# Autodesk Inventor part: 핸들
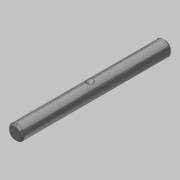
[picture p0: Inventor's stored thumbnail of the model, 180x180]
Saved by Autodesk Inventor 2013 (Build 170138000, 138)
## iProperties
Created: 2019-04
Part Number: 핸들
Material: 스테인리스강
Document SubType Name: Modeling
Designer: mduedu
Density: 1 g/cm^3
Author: mduedu
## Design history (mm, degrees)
sketch "스케치1"
  geometry: C1 r 4 at (0, 0); 1 further point
  constraints: 1 centre point, 1 coincident
  dimensions: "d0" = 8 diameter of C1
extrude "돌출1" new body sketch "스케치1" stored distance "d1" = 80; taper "d2" = 0 deg
chamfer "모따기1" distance "d3" = 1; stored, may be unused: second distance "d4" = 2, angle "d5" = 45 deg
sketch "스케치2"
  geometry: L1 (-39, 4)-(39, 4) reference; L2 (0, 4)-(0, 2); L3 (0, 2)-(2, 4); L4 (0, 4)-(2, 4); 1 further point
  constraints: 6 end point, 2 perpendicular, 1 midpoint, 1 point on line
  dimensions: "d6" = 4 diameter of L3.end L2; "d8" = 45 deg angle of L3 L2
revolve "회전1" sketch "스케치2" stored, may be unused: angle "d10" = 90 deg
node "작업점1"
  node "작업축1"
  node "작업 평면1"
node "솔리드1"
